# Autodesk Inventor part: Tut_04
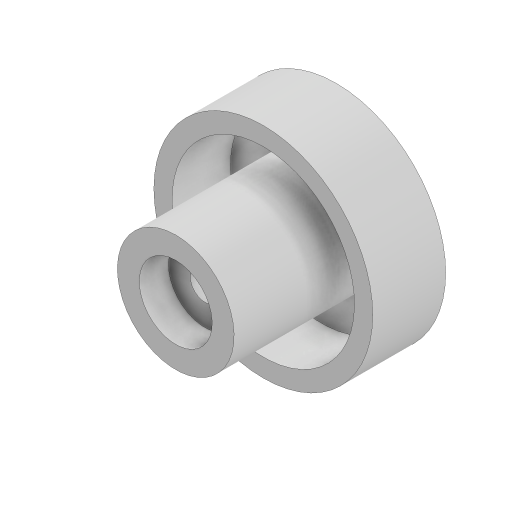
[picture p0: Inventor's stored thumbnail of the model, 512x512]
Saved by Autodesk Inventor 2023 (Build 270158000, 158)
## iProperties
Created: 2019-02
Part Number: Tut_04
Material: Generic
Document SubType Name: Modeling
Designer: LENOVO-CADCIM
Density: 1 g/cm^3
Appearance: Default
Author: LENOVO-CADCIM
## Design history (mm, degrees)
sketch "Sketch1"
  geometry: L1 (0, 0)-(0, 22); L2 (0, 22)-(4, 22); L3 (4, 22)-(4, 36); L4 (4, 36)-(10, 36); L5 (10, 36)-(10, 44); L6 (10, 44)-(16, 44); L7 (16, 44)-(16, 4); L8 (16, 4)-(25, 4); L9 (25, 4)-(25, 20); L10 (25, 20)-(30, 20); L11 (30, 20)-(30, 0); L12 (30, 0)-(0, 0); 1 further point
  constraints: 24 end point, 11 perpendicular, 1 midpoint, 1 vertical
  dimensions: "d21" = 22 distance of L1.start L1.end; "d22" = 36 distance between parallel lines of L12 L4; "d23" = 44 distance between parallel lines of L12 L6; "d24" = 25 distance between parallel lines of L9 L1; "d25" = 30 distance from line of point (30, 10) L1; "d26" = 4 distance between parallel lines of L8 L12; "d27" = 4 distance between parallel lines of L1 L3; "d28" = 10 distance between parallel lines of L5 L1; "d29" = 16 distance between parallel lines of L7 L1; "d30" = 20 distance of L10.end L11.end
revolve "Revolution1" sketch "Sketch1" stored, may be unused: angle "d31" = 90 deg
body "Solid1"
